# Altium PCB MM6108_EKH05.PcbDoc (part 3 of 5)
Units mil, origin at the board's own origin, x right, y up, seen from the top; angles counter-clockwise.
Board outline 6023.62 x 3425.2 mil, 4 copper layers (Top Layer, Ground Plane, Middle Layer, Bottom Layer), stack 76.15 mil thick; 212 components, 163 nets, 749 pads, 1477 vias.
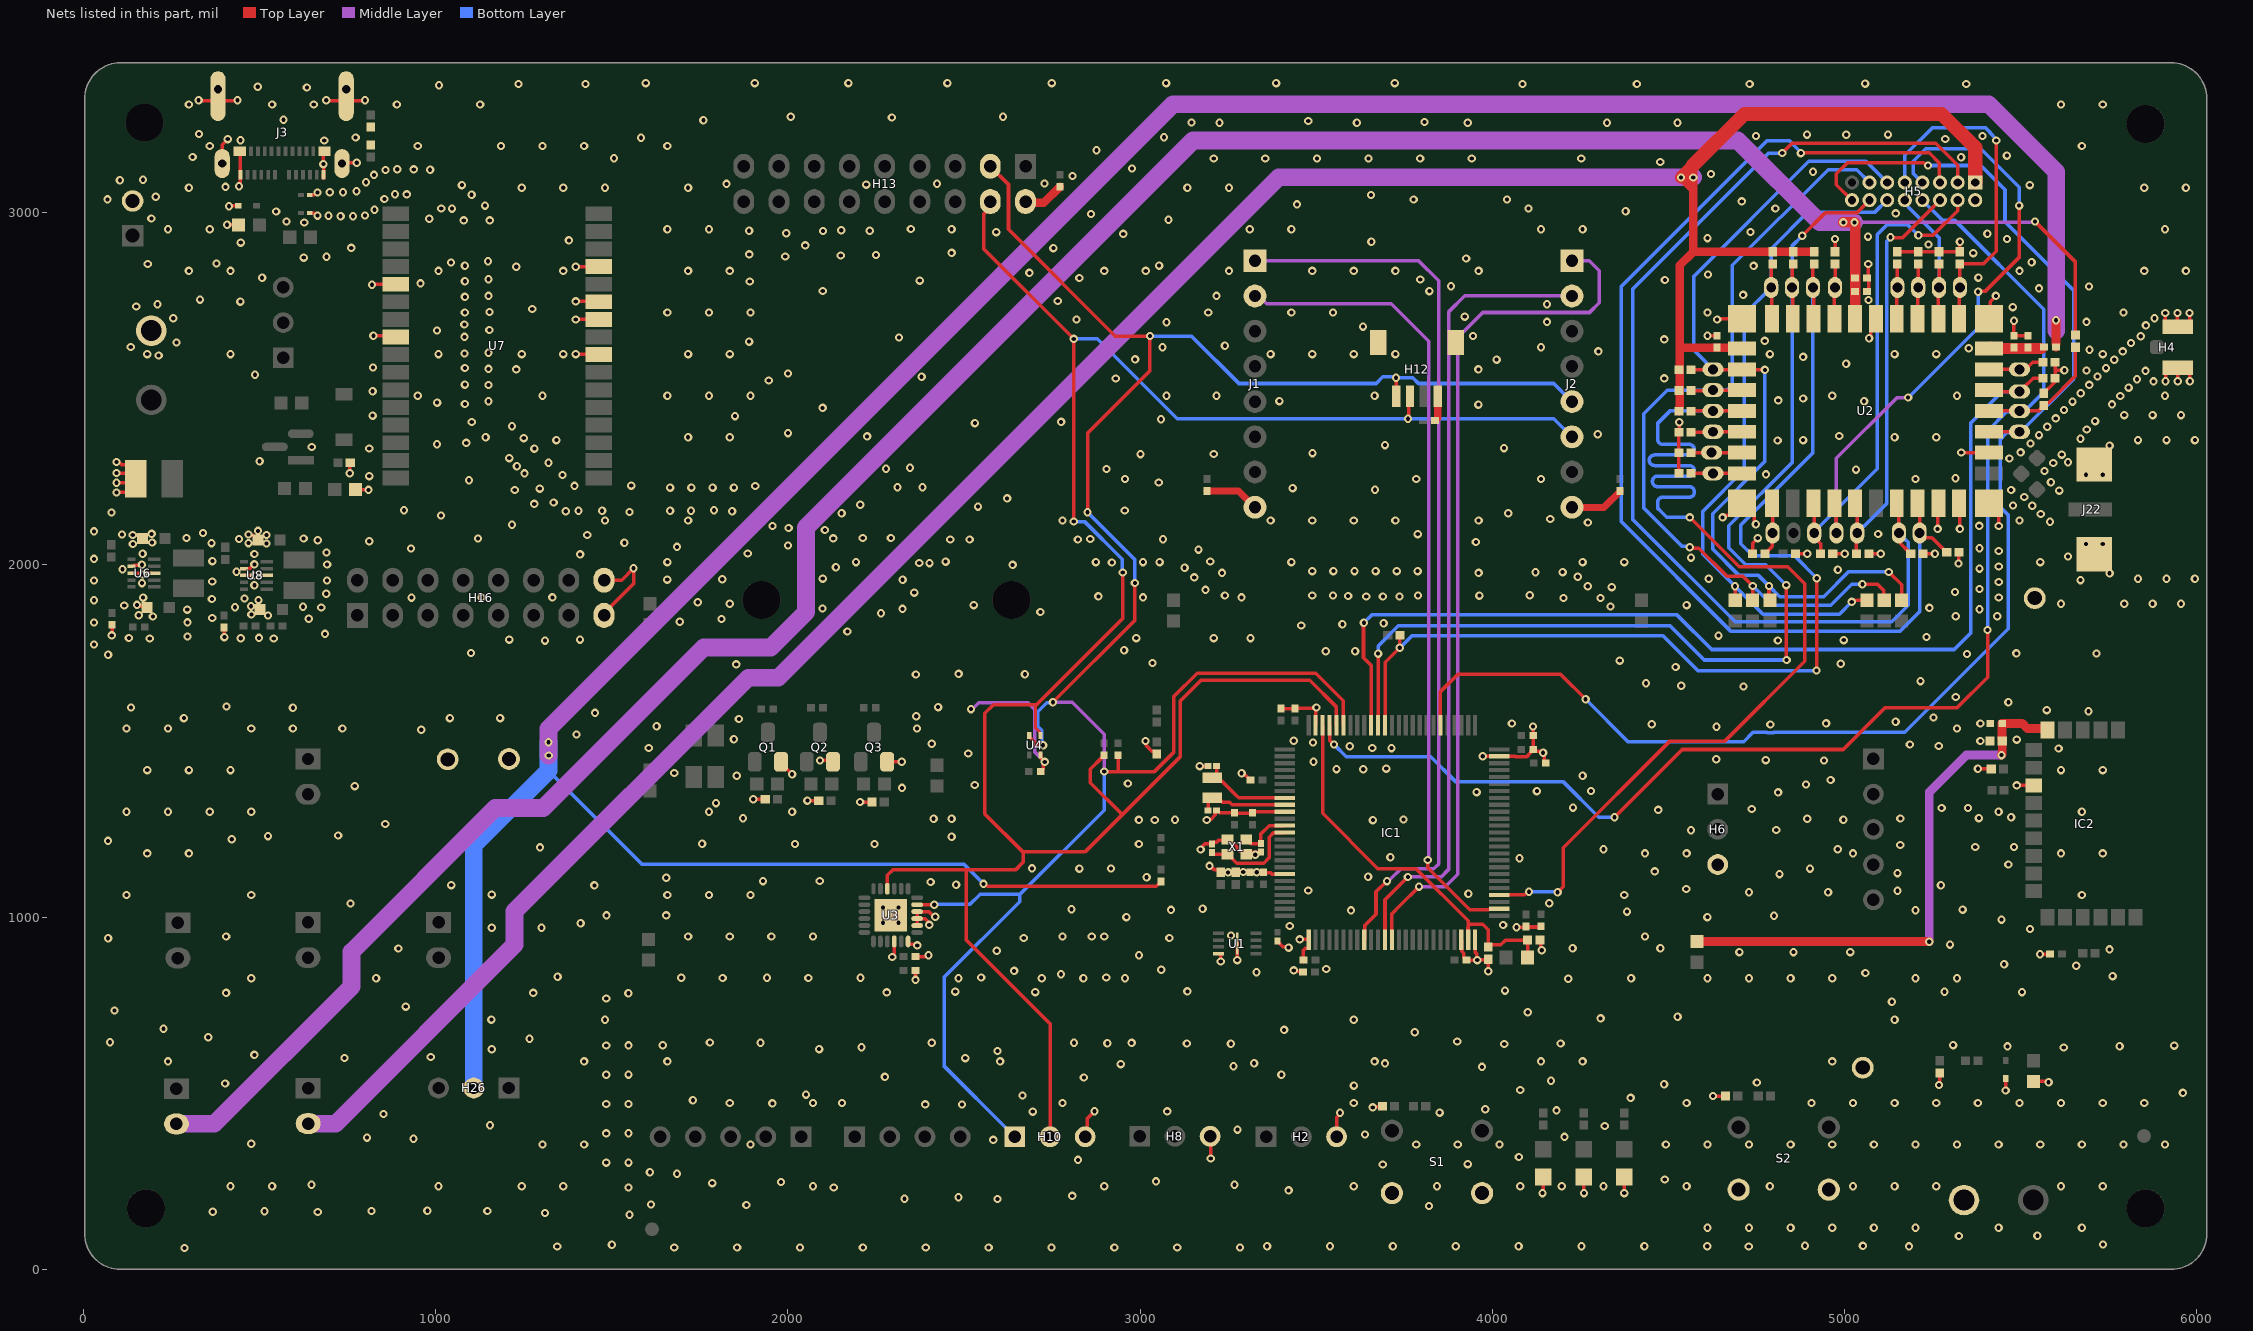
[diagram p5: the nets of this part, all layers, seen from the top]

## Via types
v1: diameter 23.62, hole 11.81, Top Layer to Bottom Layer, tented both sides, 1477 vias

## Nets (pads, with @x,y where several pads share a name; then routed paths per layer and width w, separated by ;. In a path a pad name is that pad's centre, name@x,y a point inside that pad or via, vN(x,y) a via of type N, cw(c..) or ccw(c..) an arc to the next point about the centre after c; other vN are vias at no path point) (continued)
GND: C1.1 C2.1 C3.1 C4.1 C5.1 C6.1 C7.1 C8.1 C9.2 C10.1 C11.1 C12.2 C13.2 C14.1 C15.1 C16.1 C17.1 C18.1 C19.2 C20.2 C21.1 C22.2 C23.2 C24.1 C25.1 C26.1 C27.2 C28.2 C29.2 C30.2 C31.2 C32.2 C33.2 C34.1 C35.1 C36.2 C37.1 C38.1 C39.1 C40.2 C41.1 C42.1 C43.1 C44.1 C45.1 C46.1 C47.1 C48.1 C49.2 D1.K D2.K D3.K D4.A D11.A D12.A H2.3 H4.2 H4.3 H5.2 H6.3 H8.3 H10.3 H11.1 H12.4 H12.5 H12.6 H13.2 H14.2 H15.1 H16.15 H16.16 IC1.10 IC1.19 IC1.26 IC1.48 IC1.50 IC1.74 IC1.99 IC2.8 J1.8 J2.8 J3.A1 J3.A12 J3.B1 J3.B12 J3.SH1 J3.SH2 J3.SH3 J3.SH4 J22.2 Q1.S Q2.S Q3.S R8.2 R11.1 R12.2 R14.1 R15.1 R16.1 R17.1 R18.1 R19.1 R20.1 R27.1 R28.1 R29.1 R30.1 R34.2 R37.2 R39.2 R40.2 R49.2 R52.2 R65.1 R66.1 R67.1 R69.2 R70.2 R72.2 R75.2 R77.2 S1.3 S1.4 S2.3 S2.4 TP1.1 TP2.1 TP3.1 TP4.1 U1.4 U1.9 U2.1 U2.2 U2.3 U2.12 U2.20 U2.26 U2.31 U2.37 U3.4 U3.6 U3.8 U3.9 U3.10 U3.25 U4.4 U6.2 U6.3 U6.8 U7.5 U7.8 U7.24 U7.26 U7.27 U7.29 U8.2 U8.3 U8.8 VS1.A X1.2 X1.4 | length 7882.7
  Top Layer w10: v1@81.26,1799.53 R72.2@81.26,1829.77 ; v1(93.7,2205.63) 122.32,2205.63 C49.2@147.83,2231.14 ; v1(93.7,2233.19) 136.02,2233.19 C49.2@147.83,2245 132.09,2260.75 v1(93.7,2260.75) ; v1(93.7,2292.24) 96.31,2289.64 103.2,2289.64 108.18,2284.65 122.32,2284.65 148.82,2258.16 C49.2@148.82,2231.14 ; U6.3@136.38,1976.69 160.25,1976.69 164.19,1972.76 v1(167.87,1972.76) ; U6.2@136.38,1996.38 142.91,1996.38 146.1,1999.57 165.06,1999.57 v1(165.81,2000.31) ; v1(139.61,2084.71) 158.28,2084.71 C42.1@167.87,2075.12 ; v1(151.75,1886.59) 155.39,1882.95 176.25,1882.95 C41.1@180.47,1878.74 ; v1@167.87,1970.71 v1(167.87,1972.76) ; U6.8@193.46,1976.69 193.39,1976.61 172.91,1976.61 169.06,1972.76 v1(167.87,1972.76) ; v1(326.77,3318.9) 327.36,3318.31 436.42,3318.31 v1(437.01,3318.9) ; J3.SH2@393.7,3139.37 393.7,3192.91 v1(409.45,3208.66) ; R77.2@399.49,1821.14 399.74,1820.88 399.74,1795.26 v1(400,1795) ; v1(407.75,2965.55) 439.93,2965.55 C40.2@440.47,2965 ; v1(412.84,3018) 413.83,3018.99 438.37,3018.99 VS1.A@439.36,3019.98 ; v1(441.44,3074.8) 441.44,3078.49 445.16,3082.21 445.16,3106.97 J3.A12@445.67,3107.48 ; J3.A12@445.67,3112.21 J3.B1@445.67,3181.31 ; U8.3@455.47,1970 v1(485,1970) v1@485,1967.96 ; U8.2@455.47,1989.69 472.33,1989.69 484.14,2001.5 v1(485,2001.5) ; v1(468.35,2086.26) 470.96,2083.65 481.51,2083.65 C44.1@494.84,2070.32 ; v1(496.76,1900.1) 496.76,1882.99 C43.1@506.28,1873.47 ; D12.A@640,3050 D12.A@640.91,3049.09 ; D11.A@642.2,2999.22 643.11,2998.32 656.48,2998.32 662.68,2992.11 v1@666.37,2992.11 ; D12.A@642.2,3050 643.11,3050.91 654.62,3050.91 660.79,3057.07 v1(664.47,3057.07) ; J3.A1@681.1,3098.43 681.38,3098.7 681.38,3106.97 J3.A1@681.89,3107.48 681.41,3107.96 681.41,3137.49 v1(681.1,3137.8) 681.1,3171.65 J3.B12@683.86,3174.41 ; v1(688.98,3318.9) 689.57,3318.31 798.62,3318.31 v1(799.21,3318.9) ; J3.SH1@733.07,3107.28 733.07,3130.71 744.09,3141.73 v1(775.59,3141.73) ; v1(755.76,2260.06) 756.54,2260.85 756.54,2289.22 R75.2@757.32,2290 ; R12.2@772.53,2214 773.53,2213 v1(809,2213) ; R70.2@814.21,3243.46 R70.2@815,3242.68 ; R69.2@815,3192.32 R69.2@820.27,3197.59 ; v1(818.9,2795.28) 820.47,2796.85 U7.5@886.38,2796.85 ; v1(822.83,2650.68) 882.54,2650.68 U7.8@886.38,2646.85 ; v1(1397.64,2598.43) 1461.18,2598.43 U7.24@1462.76,2596.85 ; v1(1397.64,2696.85) U7.26@1462.76,2696.85 ; v1(1397.64,2748.03) 1461.58,2748.03 U7.27@1462.76,2746.85 ; v1(1397.64,2846.46) 1462.36,2846.46 U7.29@1462.76,2846.85 ; H16.15@1477.76,1856.69 1477.76,1862.6 1561.57,1946.42 v1(1561.57,1990.43) 1527.84,1956.69 H16.16@1477.76,1956.69 ; H16.15@1497.1,1849.61 H16.15@1500.25,1846.46 ; v1(1901.57,1334.65) R65.1@1935.43,1334.65 ; Q1.S@1980.33,1440.94 1980.33,1435.69 1997.64,1418.39 1999.14,1418.39 2011.81,1405.72 v1(2011.81,1405.51) ; v1(2055.12,1330.71) R66.1@2087.4,1330.71 ; v1(2090.65,1444.88) 2124.02,1444.88 Q2.S@2127.95,1440.94 ; v1(2204.72,1326.77) R67.1@2238.58,1326.77 ; Q3.S@2281.51,1440.94 v1(2322.83,1440.94) ; v1(2296.16,887) 2296.16,890.69 2301.65,896.18 U3.4@2301.65,930.98 ; U3.6@2341.02,930.98 2341.02,925.25 2342.76,923.5 2359.81,923.5 2363.31,920 v1(2367,920) ; v1(2362,822) C38.1@2362,849 ; C37.1@2362,888 2391.31,888 2395.31,892 v1(2399,892) ; U3.8@2366.61,976.26 U3.9@2366.61,995.94 ; v1(2401,978) 2398.39,980.61 2398.39,986.86 2389.31,995.94 U3.9@2366.61,995.94 ; v1(2418,1001) 2414.31,1001 2400.41,1014.91 2367.33,1014.91 U3.10@2366.61,1015.63 U3.9@2366.61,995.94 ; U4.4@2716.54,1464.57 2717.44,1463.66 2717.44,1451.85 v1@2728.37,1440.92 ; C39.1@2718.11,1413.39 2724.93,1420.2 2724.93,1433.01 2727.7,1435.79 2727.7,1440.25 v1@2728.37,1440.92 ; v1(2728.8,1440.92) v1@2728.37,1440.92 ; H10.3@2848.9,371.72 2848.9,427.64 v1(2870.08,448.82) ; v1(3015.19,1500.19) 3017.61,1497.78 3017.61,1486.52 3033.14,1470.98 3040.04,1470.98 3047.24,1463.78 R8.2@3047.24,1462.99 ; v1(3169.17,1428.67) 3169.4,1428.9 3192.29,1428.9 C25.1@3192.52,1429.13 ; v1(3171.52,1192.19) 3171.52,1195.88 3180.47,1204.83 ; 3180.47,1204.87 3183.67,1208.07 C23.2@3203.74,1208.07 3203.74,1209.65 3207.01,1212.91 3216.85,1212.91 3222.16,1218.22 3245.78,1218.22 X1.4@3248.03,1220.47 3257.8,1210.71 3261.73,1210.71 3267.54,1204.9 3269.32,1204.9 3275.76,1198.45 3275.76,1194.9 3281.77,1188.9 3291.42,1188.9 X1.2@3301.18,1179.13 3306.69,1184.65 C22.2@3342.52,1184.65 ; v1(3188.98,1275.59) 3191.58,1278.2 3201.23,1278.2 3213.36,1290.33 3213.36,1299.88 C26.1@3216.63,1303.15 ; v1(3196.85,1145.67) 3198.99,1145.67 3209.52,1135.14 3221.14,1135.14 3228.35,1127.94 C17.1@3228.35,1127.56 ; v1(3200,315) 3200,363.78 H8.3@3214.17,377.95 ; C26.1@3216.93,1303.15 3218.5,1303.15 3225.13,1296.53 C3.1@3267.72,1296.53 ; U1.4@3222.64,895.67 3228.46,895.67 3228.54,895.59 v1(3228.54,874.21) ; C17.1@3232.28,1127.56 C21.1@3271.65,1127.56 3350.39,1127.56 3351.97,1125.98 3370.08,1125.98 3373.89,1122.17 3409.8,1122.17 IC1.19@3409.92,1122.05 ; C3.1@3267.72,1296.85 3270.08,1294.49 3316.54,1294.49 C2.1@3318.9,1296.85 ; v1(3275.59,877.95) U1.9@3275.59,925.2 ; v1(3287.84,1408.64) 3291.53,1408.64 3299.02,1401.14 3300.86,1401.14 3312,1390 C1.1@3313,1390 ; C2.1@3318.9,1296.53 3321.58,1299.21 IC1.10@3409.92,1299.21 ; C24.1@3389.76,932.68 3389.76,931.1 3404.87,915.99 3418.65,915.99 v1(3421.26,913.39) ; C14.1@3400,1592 C11.1@3440,1592 3441.5,1593.5 3498.5,1593.5 v1(3500,1595) 3498.94,1593.94 3498.94,1545.71 IC1.99@3498.03,1544.8 ; v1(3435.72,848.85) 3438.09,846.48 C5.1@3461.22,846.48 ; v1(3452.76,937.01) 3453.67,937.92 3477.44,937.92 3478.35,937.01 IC1.26@3478.35,935.51 3478.35,912.38 3477.44,911.48 3469.17,911.48 3463.31,905.62 C4.1@3463.31,874.02 ; H2.3@3557.38,376.69 3557.38,432.21 3566.93,441.76 v1(3566.93,444.88) ; v1(3660,460) 3661.3,461.3 3686.1,461.3 C19.2@3687.4,462.6 ; IC1.48@3911.42,935.51 3912.32,934.61 3912.32,903.79 3918.78,897.34 3918.78,885.16 3925.98,877.95 v1(3956.69,877.95) ; IC1.50@3950.79,935.51 3951.69,934.61 3951.69,899.44 3954.76,896.37 3954.76,879.88 v1(3956.69,877.95) ; v1(3972.44,1456.69) IC1.74@4019.21,1456.69 4064.55,1456.69 4066.43,1454.82 4096.42,1454.82 4109.43,1467.82 4109.43,1471.38 4114.43,1476.38 C8.1@4115.43,1476.38 ; v1(3988.19,846.46) C13.2@3988.19,880.31 3987.01,879.13 3957.87,879.13 v1(3956.69,877.95) ; v1(4068.34,971.2) 4068.74,971.59 C7.1@4134.97,971.59 ; C6.1@4100,972.61 4139.61,972.61 C7.1@4140,973 ; v1(4115.09,1541.3) 4115.26,1541.13 4115.26,1515.92 C10.1@4115.43,1515.75 ; C10.1@4115.75,1515.75 4115.75,1476.38 4120.75,1471.38 4135.59,1471.38 4140.05,1466.91 v1(4143.74,1466.91) 4146.35,1464.31 4146.35,1441.84 C15.1@4151.18,1437.01 ; C12.2@4134.45,935.04 4137.45,932.04 4137.45,908.64 v1(4140.05,906.03) ; v1(4141.73,216.54) 4143.7,218.5 D3.K@4143.7,262.2 ; D2.K@4258.86,262.2 4258.86,217.52 v1(4259.84,216.54) ; v1(4374.02,216.54) D1.K@4374.02,262.2 ; R28.1@4529.28,2259.84 R27.1@4529.28,2317.91 R20.1@4529.28,2376.97 4529.64,2377.33 4529.64,2404.64 v1(4530,2405) ; v1(4610.15,2650.71) 4610.22,2650.79 4637.4,2650.79 C31.2@4637.8,2651.18 ; v1(4625.98,492.13) C20.2@4661.81,492.13 ; v1(4637.8,2696.85) 4639.76,2698.82 U2.20@4708.66,2698.82 ; v1(4653.28,2135.04) 4656.96,2135.04 4662.75,2140.83 4674.29,2140.83 U2.12@4708.66,2175.2 4743.03,2140.83 4743.03,2123.7 4747.68,2119.05 v1(4747.68,2115.36) ; R29.1@4738.58,2031.5 4738.58,2061.42 v1(4753.13,2075.97) ; R30.1@4859.84,2031.5 v1(4893.7,2031.5) ; R40.2@4966.14,2031.5 v1(5000,2031.5) ; R19.1@4972.44,2888.98 v1(4972.44,2925.2) ; v1(5066.93,2854.33) 5066.93,2816.21 5068.18,2814.96 C29.2@5068.18,2775.59 ; R39.2@5068.5,2031.5 v1(5102.36,2031.5) ; v1(5069.35,2643.33) 5069.35,2647.02 5073.9,2651.56 5073.9,2684.13 U2.26@5088.58,2698.82 ; R18.1@5149.61,2889.13 R15.1@5326.77,2889.13 ; R37.2@5222.05,2031.5 v1(5255.91,2031.5) ; v1(5263.78,2102.36) 5263.78,2161.42 5271.65,2169.29 U2.3@5265.75,2175.2 ; v1(5267.72,523.62) 5269.69,525.59 C36.2@5269.69,557.87 ; U2.2@5310.12,2140.83 U2.2@5324.8,2155.51 ; v1(5322.83,2003.94) 5323.62,2004.72 5323.62,2034.65 R34.2@5324.41,2035.43 ; U2.2@5324.8,2175.2 5326.77,2173.23 v1(5326.77,2102.36) v1@5327.86,2103.45 ; R15.1@5326.77,2888.98 R15.1@5326.77,2889.13 ; v1(5326.77,2917.32) R15.1@5326.77,2889.13 ; v1(5330.71,2318.9) U2.37@5409.45,2318.9 ; v1(5377.95,1421.26) R49.2@5415.75,1421.26 ; U2.1@5409.45,2175.2 5437.01,2147.64 v1(5437.01,2110.24) ; U2.31@5409.45,2698.82 5412.69,2702.06 5412.69,2747.33 v1(5429.13,2763.78) ; v1(5456.69,507.87) D4.A@5456.69,541.34 ; v1(5480.31,2692.91) C28.2@5480.31,2650.86 C27.2@5519.69,2650.86 ; v1(5488.19,1374.02) IC2.8@5536.22,1374.02 ; R52.2@5535.43,533.46 5576.77,533.46 v1(5578.74,531.5) ; v1(5554.29,894.54) 5554.52,894.77 5582.45,894.77 C35.1@5582.68,895 ; C32.2@5565,2487.32 5565,2488.11 5597.32,2520.43 R11.1@5597.32,2530 5597.32,2552.5 ; R14.1@5597.32,2575 5597.32,2552.5 ; v1(5623.51,2552.74) 5623.27,2552.5 5597.32,2552.5 ; v1(5910,2715) 5910,2691.85 5925.67,2676.18 H4.2@5944.88,2676.18 ; v1(5910.76,2521.22) 5910.76,2544.37 5926.43,2560.04 H4.3@5944.88,2560.04 ; v1(5944.5,2715) 5944.5,2676.56 H4.2@5944.88,2676.18 ; v1(5945.26,2521.22) 5945.26,2559.66 H4.3@5944.88,2560.04 ; v1(5979,2715) 5979,2691.85 5963.33,2676.18 H4.2@5944.88,2676.18 ; v1(5979.76,2521.22) 5979.76,2544.37 5964.09,2560.04 H4.3@5944.88,2560.04
  Top Layer w20: C46.1@3188.98,2209.77 3279.4,2209.77 J1.8@3325.59,2163.58 ; C48.1@3837,2410 3838,2410 3844.65,2416.65 H12.4@3844.65,2479 ; J2.8@4225.59,2163.58 4317.02,2163.58 4362.2,2208.77 C47.1@4362.2,2209.77
  Top Layer w23.62: H13.2@2674.41,3031.5 2677.48,3028.43 2726.53,3028.43 C45.1@2771.65,3073.55
  Middle Layer w10: v1(2519.68,1590.55) 2523.37,1590.55 2541.08,1608.26 2681.74,1608.26 2700,1590 2700,1469.72 v1(2728.8,1440.92)
  other v1: 286.55,60.7 1677.17,62.24 1855.64,62.24 2034.12,62.24 2212.6,62.24 2391.08,62.24 2569.55,62.24 2748.03,62.24 2926.51,62.24 3104.99,62.24 3283.46,62.24 1345,65 4727.36,65.11 3360.3,65.54 3538.78,65.54 3717.26,65.54 3895.73,65.54 4074.21,65.54 4252.69,65.54 4431.17,65.54 4609.64,65.54 5182.36,65.4 5051.47,66.91 4887.17,67.35 1500,70 5733.15,70.84 5324.1,94.78 5546.93,95.48 4610.23,118.11 4728.34,118.11 4846.45,118.11 4964.56,118.11 5082.67,118.11 5200.78,118.11 5437,118.11 5673.22,118.11 1550,155 1310.31,159.96 665.17,163.15 366.82,163.79 514.08,165.06 817.53,165.7 1146.47,165.7 976.26,166.34 3820,180 1881.89,182.81 1611,184 2595,200 2330.71,200.79 2484.25,204.72 2807.09,208.66 3421.26,224.41 1547.24,232.28 2129.92,232.28 417.32,236.22 535.43,236.22 1007.87,236.22 1244.09,236.22 1362.2,236.22 2070.86,236.22 2897.64,236.22 3606.3,236.22 3842.52,236.22 4078.74,236.22 4196.85,236.22 4314.96,236.22 4551.18,236.22 4787.4,236.22 5023.62,236.22 5141.73,236.22 5259.84,236.22 5614.17,236.22 5732.28,236.22 647.23,240.26 3267.72,240.16 1785,245 1980.31,248.03 3045,250 4489.15,255.03 1685.04,271.65 1607.81,275.59 3688.62,297.74 3929.66,298.89 1484.25,303.15 1547.24,303.15 2823.37,311.05 4075.01,319.11 1303.15,354.33 1421.26,354.33 1893.7,354.33 3783.46,354.33 3901.57,354.33 4019.68,354.33 4492.12,354.33 4610.23,354.33 4728.34,354.33 4846.45,354.33 4964.56,354.33 5082.67,354.33 5200.78,354.33 5318.89,354.33 5437,354.33 5555.11,354.33 5673.22,354.33 5791.34,354.33 5909.45,354.33 476.38,356.81 2582.9,367.67 937,371 805,374 4204.4,376.3 3637.87,383.09 1484.25,386.28 1547.24,386.39 3276.28,396.88 4318.48,407 1154,409 851.69,441.07 3850,445 2695.03,447.83 3076.74,448.71 4181.52,451.55 3979.26,454.59 2493.96,467.92 2389.76,468.5 1484.25,469.42 1547.24,469.63 1955.74,471.26 1834.64,472.44 2070.86,472.44 2153.54,472.44 2779.53,472.44 3606.3,472.44 4551.18,472.44 4905.51,472.44 5023.62,472.44 5141.73,472.44 5259.84,472.44 5377.95,472.44 5496.06,472.44 5614.17,472.44 5732.28,472.44 5850.39,472.44 1730.03,480.42 4392.17,486.84 2665.91,493.86 2051.18,496.06 5959.94,501.23 4079.01,509.38 3606.53,521.79 4487.35,525.66 402,528 4750.61,530.59 4165.86,535.74 2840,545 2275.08,546.52 1484.25,552.55 1547.24,552.87 3400.65,552.8 3970,575 3264.75,576.68 2944.88,582.68 3695,585 3323.42,585.44 240.16,590.55 1421.26,590.55 1657.48,590.55 2602.36,590.55 3665.35,590.55 4137.79,590.55 4255.9,590.55 4964.56,590.55 741,600 2503.03,599.84 986,603 485,609 2595,620 1159,625 2088.47,625.21 5621.73,629.82 2208.76,630.63 5462.09,633.21 5780.4,633.7 5935.68,635.15 1484.25,635.68 1547.24,636.11 1644.45,636.53 5307.78,636.61 4033.34,639.87 3257.32,640.49 2906.64,641.86 3132.4,641.36 4193.5,641.38 1921.77,643.22 2407.97,643.29 2975.47,643.19 1778.22,644.25 2811.93,643.46 75,645 3900.07,647.06 1266,655 354,659 3779.53,673.23 3408.42,680 227,683 1158,709 1480.31,708.66 3606.3,708.66 5141.73,708.66 4307.09,712.6 4525.52,717.18 4100,730 88,735 915,746 5133.86,759.84 1484.25,769.1 1546.8,784.08 405,785 1277,785 2280.33,786.57 2701.84,787.21 5503.33,787.03 5283.03,788 2474.76,788.59 3133.86,789.21 4035.43,791.34 4215,825 476.38,826.77 830.71,826.77 2484.25,826.77 2720.47,826.77 2838.58,826.77 2956.69,826.77 4393.7,826.77 4610.23,826.77 4728.34,826.77 4846.45,826.77 4964.56,826.77 5200.78,826.77 5318.89,826.77 1696.79,827.77 1814.53,827.35 1940.22,828.18 2057.96,827.35 2205.95,828.13 2548.29,828.72 2903.31,828.83 1346,831 5760.51,832.64 2775.14,838.04 5058.61,841.26 3330.21,843.77 2641.89,847.38 3059.47,850.56 3527.92,852.84 5657.13,861.91 5452.39,866.37 2996.35,891.79 4700.79,900.79 4854.33,900.79 5015.75,900.79 2592.5,904.65 5751.52,908.56 894,911 4227.62,911.67 4476.58,911.87 5299.07,921.94 70,940 2669.29,940.94 3082.68,940.94 405,944.88 1716.53,944.88 1834.64,944.88 1952.75,944.88 2070.86,944.88 2779.53,944.88 2862.2,944.88 2897.64,944.88 4433.07,944.88 3257.83,947.83 5525.89,966.35 1159,970 1300,970 3424.4,974.65 4030.12,977.83 1411.26,982.46 2270.15,984.13 2313.46,984.13 5444.8,992.94 2960.63,1000 4610,1000 4799.21,1003.94 1485,1005 1654.6,1005 4381.89,1015.75 3598.41,1019.19 5200.79,1019.68 3087.21,1020.74 5334.75,1021.35 2804.8,1022.54 3177.17,1023.62 2270.15,1027.44 2313.46,1027.44 758,1039 4161.21,1039.41 122.05,1062.99 476.38,1062.99 1657.48,1062.99 1775.59,1062.99 1893.7,1062.99 4374.01,1062.99 5673.22,1062.99 1159,1064 3931.5,1066.57 4728.35,1070.87 4952.76,1070.87 5150,1075 3477.1,1075.45 4550,1080 1450.35,1090.17 1044,1091 5272.81,1090.55 2477.32,1092.1 2405,1100 1929.13,1102.36 2090.23,1102.39 1654.6,1111.72 3018.06,1113.34 3646.93,1114.48 4814.96,1122.05 5150,1125 3249.49,1127.22 3292.43,1128.04 3330.56,1127.49 4460.63,1129.92 2827.19,1137.8 2917.24,1137.94 4901.57,1137.8 2692.64,1138.38 5464.57,1149.61 4076.84,1167.07 3710,1170 3326.69,1177.16 181.1,1181.1 299.21,1181.1 4433.07,1181.1 4551.18,1181.1 5023.62,1181.1 5614.17,1181.1 5732.28,1181.1 4314.96,1192.91 4980.31,1192.91 1296,1198 5370.63,1199.21 5480.52,1198.96 5157.48,1204.72 2019.68,1207.81 2245.64,1207.81 2996.06,1207.81 1756.24,1208.35 69.61,1216.53 421,1221 2464.57,1228.35 524,1230 723,1232 4563.62,1246.49 4805.55,1247.38 856.69,1264.2 2996.14,1276.16 3041.24,1275.59 3660.42,1275.44 3098.68,1276.47 4996.06,1276.4 3747.25,1277.35 2413.39,1279.53 2464.57,1279.53 4893.7,1279.53 5157.88,1279.86 1872.1,1280.56 5380.76,1281.07 5472.44,1283.46 122.05,1299.21 240.16,1299.21 358.27,1299.21 476.38,1299.21 1775.59,1299.21 2011.81,1299.21 5437,1299.21 5673.22,1299.21 4470.38,1304.55 4736.22,1307.09 5275,1310 5350,1310 4228.35,1311.02 1795.61,1323.7 3955,1355 4811.02,1354.33 4125.98,1357.68 4279.53,1358.27 2323.66,1367.09 770,1372 2530.11,1375.18 4890.2,1376.47 2964.78,1379.43 4959.95,1389.39 1854.33,1401.57 4255.91,1401.57 1677.17,1409.45 181.1,1417.32 299.21,1417.32 417.32,1417.32 5614.17,1417.32 5732.28,1417.32 3557.16,1420.14 3633.03,1419.85 3698.27,1421.62 3491.76,1441.06 4940.94,1444.88 4775.76,1445.84 4635.3,1448.25 2511.81,1464.57 5607.16,1478.66 1604.87,1480.16 3658.51,1480.06 3713.12,1479.77 3595,1485 5266.89,1485.93 5185,1490 2408.31,1492.14 3490.33,1495.59 5385,1500 3435.72,1500.72 5488.19,1503.94 1846.44,1505.25 1399.43,1518.36 959,1532 122.05,1535.43 240.16,1535.43 476.38,1535.43 594.49,1535.43 734.94,1535.43 2366.14,1535.43 5318.89,1535.43 4635.8,1540.63 1627,1542 4788.98,1546.72 4452.06,1547.81 4055,1549.92 4947.26,1550.15 5385,1550 5144.57,1554.79 1860.53,1562.5 285,1565 1040,1565 1182.88,1565 5251.97,1566.93 2364.25,1570.25 1452,1580 5692.17,1584.73 5573.65,1587.77 135,1595 594.49,1594.49 2426.13,1596.24 405.99,1598.01 5464.57,1610.24 5315,1625 4712.8,1654.72 4536,1657 4435.77,1664.04 5215,1670 2363.15,1689.04 2672.51,1689.64 2484.37,1690.54 4520,1710 1853.22,1717.57 4988.71,1719.36 3034.85,1721.52 4361.1,1728.35 70,1745 5347.2,1747.27 5487.19,1748.78 5714.58,1748.54 1100,1750 3526.58,1754.69 3610,1755 2954.37,1757.89 30.01,1773.79 1310,1785 4810.21,1785.14 4997.16,1786.4 1208.66,1787.81 1409.45,1787.81 188.29,1791.1 540.33,1791.1 446.34,1791.95 2988.67,1792.15 3208.66,1792.15 3312.81,1792.15 128.9,1792.38 498.04,1792.81 5232.28,1795.28 295.1,1796.65 4641.73,1799.21 80,1800 685.44,1804.21 2168.52,1811.19 3457.12,1827.83 3573.84,1831.65 3690.99,1834.23 30.01,1836.43 295.1,1836.81 1692.91,1838.58 639.45,1847.17 1811.02,1846.46 365.4,1849.27 197.04,1853.55 5314.96,1854.33 5433.07,1854.33 156.89,1856.87 523.69,1856.53 476.57,1858.99 2264.16,1862.59 2716.54,1866.14 294.67,1873.13 5382.7,1874.02 2325.05,1875.27 2097.87,1876.18 5240.16,1877.95 675.13,1879.1 429.95,1879.99 623.2,1881.04 4335,1881.82 475.65,1882.69 115.79,1884.55 2527.56,1885.83 4551.18,1885.83 1834.64,1889.76 5614.17,1889.76 5793.31,1889.76 5874.02,1889.76 5954.72,1889.76 1743.94,1893.91 30.01,1899.73 364.44,1903.39 457.25,1904.66 4201.62,1906.05 4306.55,1906.08 169.23,1907.16 931.38,1906.98 5437.01,1907.26 1130.08,1907.46 1331.15,1907.93 3007.81,1907.81 3287.4,1907.92 2881.25,1910.61 3641.58,1910.48 3688.83,1910.48 3736.07,1910.48 3590.22,1911.67 3962.83,1912.7 3240.16,1913.39 3488.19,1913.39 3547.24,1913.39 3788.67,1913.39 4105.91,1913.96 689.18,1917.93 2358.27,1921.26 5313.02,1923.12 3185.04,1929.13 5382.7,1931.76 4338.58,1937.01 4270.3,1939.31 485,1942.44 166.21,1948.34 5437.01,1951.3 365.44,1952.76 30.01,1955.67 691.38,1955.93 5669.29,1956.69 1657.45,1958.27 2325.55,1957.92 1813.47,1959.13 2098.81,1961.01 4614.17,1960.63 5832.68,1960.63 5913.39,1960.63 5994.09,1960.63 3153.54,1964.57 4242.11,1966.5 5751.97,1976.38 3232.28,1977.42 3960.63,1977.42 4122.29,1979.25 4199.15,1979.59 434.54,1980.69 3488.19,1982.42 3548.23,1982.42 3608.27,1982.42 3668.31,1982.42 3728.35,1982.42 3787.4,1982.42 4980.56,1986.16 110.85,1987.75 5382.7,1989.5 3125.98,1992.13 2136.01,1993.54 5437.01,1995.33 2637.8,2000 691.66,2001.1 2372.79,2005.16 2401.61,2005.11 2919.56,2007.01 1657.48,2007.87 2192.91,2007.87 2874.02,2007.87 3007.81,2007.87 3055.12,2007.87 3429.13,2007.87 4255.91,2007.87 4374.01,2007.87 5555.11,2007.87 2447.44,2009.26 3198.67,2009.69 365.95,2010.72 30.01,2017.1 4563.34,2020.57 5633.86,2023.62 1410,2030 485.02,2030.89 167.87,2031.81 1885.98,2032.31 690,2035 5437.01,2039.37 3165.35,2043.31 929.96,2046.41 5382.7,2047.24 1685.04,2051.18 2000,2055.12 5685.04,2059.06 5732.28,2059.06 140.07,2059.43 519.69,2060.96 363.47,2061.91 468.46,2061.8 1535.43,2062.99 194.77,2063.8 3952.81,2065 811.02,2066.93 665,2070 2460.63,2072.05 2515.75,2072.05 2822.83,2072.05 3064.87,2072.62 441.29,2073.64 2858.22,2073.73 625,2075 1120,2075 2128.56,2075.37 2212.09,2076.21 2292.02,2076.2 292.45,2076.62 519.49,2085.01 1430,2085 109.27,2086.33 3788.02,2087.27 193.5,2088.15 5094.77,2087.71 339.02,2090.35 30.01,2095.23 495.25,2096.71 2104.75,2099.21 2001.86,2104.53 1956.24,2110.69 5381.92,2110.73 1216.54,2114.17 4270.69,2120.25 5582.51,2122.63 1480.31,2125.98 1716.53,2125.98 2779.53,2125.98 3370.08,2125.98 3488.19,2125.98 3606.3,2125.98 3724.41,2125.98 3960.63,2125.98 5496.06,2125.98 4164.17,2130.29 1015,2140 5556.48,2144.68 2152.38,2146.83 4044.68,2146.41 79.59,2148.66 1550,2150 1369.03,2152.45 1841.47,2152.32 1405.51,2153.54 1472.44,2153.54 1665.35,2153.54 1724.41,2153.54 2955.85,2154.27 910,2155 1790,2155 2539.37,2165.35 5532.14,2167.87 5477.84,2168.78 2205.22,2170.66 1279.53,2173.23 1334.65,2177.17 2622.05,2188.98 5509.59,2192.81 5608.87,2210.75 1224.41,2212.6 5472.44,2212.6 3666.68,2213.32 1295.28,2216.54 3432.69,2217.88 1665.35,2219.27 1725.72,2219.27 1786.09,2219.27 1846.46,2219.27 2311.02,2220.47 2381.89,2220.47 1907.05,2224.12 1393.7,2224.41 1555,2225 3052.6,2234.04 5585.12,2234.55 1094.49,2240.16 2956.69,2244.09 3783.46,2244.09 4137.79,2244.09 5200.78,2244.09 5314.42,2245.83 811.02,2251.97 1360,2255 5685.04,2255.91 5732.28,2255.91 4776.63,2256.93 1251.97,2259.84 5567.16,2266.82 5032.07,2270.54 2904,2272.2 2278.36,2272.82 2346.46,2275.59 1230.36,2280.12 1320,2290 5592.08,2289.39 5633.86,2291.34 500.13,2294.19 5467.47,2302.15 1208.66,2303.15 5615.86,2313.17 3000.55,2314.44 3208.66,2314.96 3488.82,2317.33 5499.35,2319.41 1280,2330 811.02,2330.71 4032.63,2331.59 648.05,2334.6 5751.97,2338.58 3695,2340 1003.55,2342.52 5527.59,2344.57 1086.61,2346.46 4809.41,2353.02 1342.52,2354.33 4881.89,2354.33 5832.68,2354.33 5913.39,2354.33 5994.09,2354.33 5669.29,2358.27 1250,2360 1141.73,2362.2 1716.53,2362.2 1834.64,2362.2 5141.73,2362.2 5259.84,2362.2 2224.63,2364.95 4984.25,2366.14 5551.37,2368.34 4298.9,2370.75 2000,2374.02 5687.18,2384.49 5575.14,2392.12 1216.54,2393.7 2530.53,2402.44 1102.36,2405.51 2775.43,2406.05 5710.96,2408.26 3059.06,2413.39 5598.92,2415.89 1849.46,2422.37 820.84,2423.86 5793.31,2425.2 5874.02,2425.2 5954.72,2425.2 5622.69,2439.67 2098.42,2445.78 3960,2455 5758.51,2455.81 1082.68,2456.69 1003.94,2460.63 5646.47,2463.44 1149.61,2464.57 3395,2465 5055.12,2464.57 4811.46,2467.06 4881.89,2472.44 5782.28,2479.59 948.82,2480.31 1303.15,2480.31 1657.48,2480.31 1775.59,2480.31 1893.7,2480.31 3074.8,2480.31 3216.54,2480.31 3665.35,2480.31 4964.56,2480.31 5318.89,2480.31 5909.45,2480.31 5670.24,2487.21 820.94,2492.97 5806.05,2503.36 1149.61,2510.5 5694.01,2510.99 1082.68,2511.81 5876.44,2521.06 1945.46,2523.51 5829.83,2527.13 2930.47,2529.27 4487.7,2529.55 2379.46,2533.92 5717.79,2534.76 487.05,2539.86 2000,2543.31 5853.6,2550.91 5686.19,2551.97 1228.35,2555.12 3960,2555 1149.61,2556.43 1082.68,2559.06 5741.56,2558.54 822.11,2560.57 5003.94,2570.87 4011.81,2582.68 5765.34,2582.31 2985.39,2583.51 4881.89,2590.55 213.28,2594.37 181.1,2598.42 417.32,2598.42 1007.87,2598.42 1244.09,2598.42 1362.2,2598.42 1716.53,2598.42 1834.64,2598.42 3370.08,2598.42 3488.19,2598.42 3606.3,2598.42 3724.41,2598.42 4787.4,2598.42 5141.73,2598.42 5259.84,2598.42 5732.28,2598.42 1081.46,2600.19 1149.61,2602.36 4300.52,2606.28 5789.11,2606.09 5694.91,2610.87 5352.27,2615.01 3062.99,2618.11 4137.8,2618.11 134.34,2618.72 3240.16,2622.05 5812.89,2629.86 264.19,2631.26 1889.76,2633.86 4772.83,2636.03 4487.77,2640.16 2314.96,2645.67 1081.46,2647.43 3944.88,2649.61 5840.29,2649.34 1003.55,2665.35 1152.35,2666.67 3632.19,2676.47 5855,2680 1081.22,2682.23 3074.8,2688.98 4155,2690 5686.19,2689.93 2818.9,2696.85 255,2700 5879.46,2700.01 3921.26,2704.72 1082.68,2716.54 1657.48,2716.53 1775.59,2716.53 1893.7,2716.53 3192.91,2716.53 3429.13,2716.53 3547.24,2716.53 4610.23,2716.53 5791.34,2716.53 1152.62,2718.11 1274.13,2726.51 5476.87,2731.87 149.84,2733.81 210,2740 4155,2740 445.41,2747.45 2765.9,2749.27 5067.4,2752.03 330.99,2753.01 1082.68,2760.83 1149.61,2763.78 3216.54,2763.78 4711.53,2766.53 2098.59,2777.79 3820.71,2777.29 5551.68,2785 3882.18,2791.25 5693.22,2790.42 956.69,2799.21 1082.68,2805.12 1891.62,2804.51 2374.02,2807.09 4489.3,2808.72 3795,2810 1149.61,2811.02 507.17,2815 2827.2,2814.44 5379.34,2815.43 4611.77,2824.31 2685.34,2828.95 299.21,2834.64 417.32,2834.64 1007.87,2834.64 1362.2,2834.64 1716.53,2834.64 1834.64,2834.64 2897.64,2834.64 3015.75,2834.64 3251.97,2834.64 3488.19,2834.64 3606.3,2834.64 3724.41,2834.64 3960.63,2834.64 5496.06,2834.64 5850.39,2834.64 5968.5,2834.64 1228.35,2846.46 4741.44,2848.97 1082.68,2849.41 3053.61,2849.67 182.26,2854.35 377.7,2855.65 1043.31,2858.27 5530.59,2859.32 1148.4,2862.2 3925.2,2870.08 625.31,2872.34 690,2875 1992.31,2875.63 2149.58,2878.51 2250,2880 1889.93,2881.6 5365,2885 2464.57,2885.83 760,2900 2753.39,2899.32 2048.86,2907.18 5237.63,2909.76 446.46,2914.99 3656.21,2917.5 1377.95,2921.26 5460.77,2925.17 4610.33,2927.71 5066.07,2931.93 2951.73,2939.75 5405,2940 1995.18,2941.35 2591.42,2944.67 4732.28,2944.88 2099.15,2947.87 1889.76,2948.82 2232.28,2948.82 2151.38,2949.96 240.16,2952.75 358.27,2952.75 1657.48,2952.75 1775.59,2952.75 2464.57,2952.76 3311.02,2952.75 3429.13,2952.75 4137.79,2952.75 4255.9,2952.75 5909.45,2952.75 2348.91,2953.52 626.85,2971.91 576.2,2975.01 1079.65,2978.1 1153.25,2978.18 3080,2980 192.59,2983.2 981.57,2982.55 730,2990 765,2990 664.53,2991.45 695.71,2991.36 799.05,2991.92 2860.26,2996 5144.83,2997.96 546.88,3003.31 4377.95,3003.94 826.14,3008.12 1015.7,3011.96 1046.24,3011.51 4102.36,3011.81 4803.15,3011.81 1140,3020 3444.88,3023.62 4707.72,3032.02 68.07,3037.82 3776.21,3037.5 4041.21,3037.5 854.07,3038.57 205,3045 3655,3050 1101.8,3050.62 884.51,3052.25 917.75,3051.97 699.19,3057.9 736.9,3057.9 775.16,3060.69 299.21,3070.86 1244.09,3070.86 1362.2,3070.86 1480.31,3070.86 1716.53,3070.86 3133.86,3070.86 3251.97,3070.86 5850.39,3070.86 5968.5,3070.86 403.05,3073.19 1074.24,3078.18 5525.33,3078.17 2222.34,3079.53 1825.67,3081.79 2423.25,3082.17 2728.35,3082.68 802.2,3086.38 103.31,3091.86 168.7,3093.54 2807.56,3104.18 824.75,3107.28 4620.58,3109.78 4909.89,3116.31 857.55,3121.3 984.08,3121.86 890.66,3123.2 937.71,3122.98 2976.8,3125.21 4476.38,3143.84 3208.66,3153.54 3355.12,3153.54 3501.57,3153.54 3648.03,3153.54 3794.49,3153.54 3940.94,3153.54 4251.97,3153.54 1506.09,3154.37 5330.37,3157.14 309.92,3157.83 5460.2,3161.8 2876,3177 358.27,3188.98 948.82,3188.98 1185.04,3188.98 1303.15,3188.98 1421.26,3188.98 1657.48,3188.98 5673.22,3188.98 683.37,3204.8 445.52,3205.44 5285.13,3209.14 1582.68,3212.6 772.48,3213.33 3067.35,3213.9 4748.12,3217.4 5390.85,3217.62 5004.3,3220.94 4892.91,3221.57 5122.78,3221.41 327.72,3223.12 3225,3255 3615,3255 3930,3255 4325,3255 4525,3255 3145.67,3255.91 3806.79,3257.51 3476.84,3259.98 1759.84,3262.22 567.92,3263.76 2295,3270 2007.87,3272.19 2610.24,3272.19 299.21,3307.09 535.43,3307.09 653.54,3307.09 889.76,3307.09 1125.98,3307.09 5614.17,3307.09 5732.28,3307.09 634.06,3355.07 494.65,3357.25 1009.36,3361.65 1235,3365 1425,3365 4085,3365 4410,3365 4730,3365 5345,3365 5057.82,3366.3 1596.28,3367.81 1905.48,3367.81 2171.32,3367.81 2452.46,3367.81 2748.91,3367.81 3073.4,3367.75 3385.83,3367.75 3722.39,3367.75
I2C_SCL: H10.1 H12.1 H13.3 IC1.95 J2.5 R82.2 U3.11 U4.2 | length 6513
  Top Layer w10: U3.11@2366.61,1035.31 2414.68,1035.31 v1(2415,1035) ; H13.3@2558.98,3146.92 H13.3@2574.41,3131.5 2625.98,3079.92 2625.98,2952.76 2929.13,2649.61 v1(3027.56,2649.61) 3027.56,2551.18 2850.39,2374.02 v1(2850.39,2149.61) ; U4.2@2685.04,1515.75 2685.94,1514.84 2685.94,1510.91 2707.42,1489.43 2723.03,1489.43 v1(2724.27,1488.19) ; v1(2751.97,1610.24) 2985,1843.27 2985,1948.67 v1(2984.84,1948.83) ; v1(2897.64,1413.39) 2937.01,1413.39 ; R82.2@2937.01,1459.38 2937.01,1413.39 ; IC1.95@3576.77,1544.8 3576.77,1614.17 3498.03,1692.91 3161.42,1692.91 3094.49,1625.98 3094.49,1467.51 3040.36,1413.39 2937.01,1413.39 ; v1(3725.85,2531.18) 3726.19,2530.84 3726.19,2479.34 H12.1@3726.54,2479
  Middle Layer w10: v1(2751.97,1610.24) 2807.09,1610.24 2897.64,1519.69 v1(2897.64,1413.39)
  Bottom Layer w10: v1(2415,1035) 2416,1036 2516,1036 2545.5,1065.5 2657.93,1065.5 2657.93,1043.93 2443,829 2443,577.39 2629.92,390.47 H10.1@2657.48,390.47 ; 2657.93,1064.27 2897.64,1303.98 v1(2897.64,1413.39) ; v1(2724.27,1488.19) 2721.67,1490.8 2721.67,1499.66 2720.47,1500.86 2720.47,1529.91 2708.79,1541.59 2708.79,1567.08 2708.79,1582.81 2734.38,1608.39 2750.13,1608.39 v1(2751.97,1610.24) ; v1(2850.39,2149.61) 2985,2015 2985,1948.98 v1(2984.84,1948.83) ; v1(3027.56,2649.61) 3145.67,2649.61 3280.28,2515 3670,2515 3688.78,2533.78 3723.24,2533.78 v1(3725.85,2531.18) 3726.35,2531.68 3773.32,2531.68 3790,2515 4174.17,2515 J2.5@4225.59,2463.58
I2C_SDA: H10.2 H12.2 H13.4 IC1.96 J2.6 R85.2 U3.16 U4.1 | length 6809.5
  Top Layer w8: 2702.56,1603.27 2702.56,1600.2 2702.56,1537.6 2714.63,1525.53 2714.63,1521.59 U4.1@2716.54,1519.68
  Top Layer w10: U3.16@2281.96,1080.59 2281.96,1118.96 2297,1134 2505.92,1134 ; H13.4@2574.41,3031.5 2574.41,3014.5 2555.12,2995.2 2555.12,2897.64 v1(2811.02,2641.73) v1(2811.02,2123.14) ; 2667.35,1185 2667.35,1155.59 2645.75,1134 2505.92,1134 ; 2702.56,1600.2 2950.18,1847.82 v1(2950.18,1978.48) ; 2702.56,1603.27 2583.58,1603.27 2559.06,1578.74 2559.06,1293.01 2667.06,1185 2843.02,1185 3114.17,1456.16 3114.17,1614.17 3172.42,1672.42 3481.12,1672.42 3557.09,1596.46 IC1.96@3557.09,1544.8 ; H10.2@2744.09,380.66 2744.09,696.85 2505.92,935.02 2505.92,1134 ; R85.2@2897.64,1459.38 2897.64,1458.38 2892.64,1453.38 2891.64,1453.38 2858.27,1420.01 2858.27,1381.89 2947.25,1292.91 ; v1(3760,2415) 3762.61,2417.61 3762.61,2475.7 H12.2@3765.91,2479
  Bottom Layer w10: v1(2811.02,2123.14) 2841.86,2123.14 2948.54,2016.46 2948.54,1980.11 v1(2950.18,1978.48) ; v1(2811.02,2641.73) 2878.27,2641.73 3105,2415 v1(3760,2415) 4174.17,2415 J2.6@4225.59,2363.58
MIKRO_AN: IC1.34 J1.1 | length 2561.3
  Top Layer w10: IC1.34@3635.83,935.51 3636.73,936.42 3636.73,975.9 3669.29,1008.46 3669.29,1071.93 3699.72,1102.36 v1(3700.79,1102.36)
  Middle Layer w10: J1.1@3325.59,2863.58 3789.96,2863.58 3847.03,2806.51 3847.03,1151.06 3833.76,1137.8 3740.16,1137.8 3711.54,1109.17 3711.28,1109.17 3704.47,1102.36 v1(3700.79,1102.36)
MIKRO_INT: IC1.37 J2.2 | length 2281.6
  Top Layer w10: IC1.37@3694.88,935.51 3694.88,1049.21 v1(3759.84,1114.17)
  Middle Layer w10: v1(3759.84,1114.17) 3854.33,1114.17 3875.31,1135.15 3875.31,2717.83 3921.06,2763.58 J2.2@4225.59,2763.58
MIKRO_PWM: IC1.38 J2.1 | length 2453.9
  Top Layer w10: IC1.38@3714.57,935.51 3714.57,1009.84 3736.89,1032.17 v1(3791.34,1086.61)
  Middle Layer w10: v1(3791.34,1086.61) 3866.14,1086.61 3901.59,1122.06 3901.59,2645.69 3972.44,2716.54 4275.59,2716.54 4303.15,2744.09 4303.15,2834.65 4274.21,2863.58 J2.1@4225.59,2863.58
MIKRO_RST: IC1.52 J1.2 | length 2296.6
  Top Layer w10: v1(3816.26,1162.1) 3816.26,1140.07 3935.49,1020.84 3989.32,1020.84 3991.19,1022.72 4018.31,1022.72 IC1.52@4019.21,1023.62
  Middle Layer w10: J1.2@3325.59,2763.58 3336.91,2763.58 3358.95,2741.55 3712.8,2741.55 3819.26,2635.08 3819.26,1174.73 3818.87,1174.34 3818.87,1164.71 v1(3816.26,1162.1)
MM_BUSY: IC1.91 pad.31@5496.06,2492.13 R11.2 U2.34 | length 3035.3
  Top Layer w10: v1(3634.87,1835.92) 3633.79,1834.85 3633.79,1736.29 3655.51,1714.57 IC1.91@3655.51,1544.8 ; U2.34@5409.45,2496.06 5413.39,2492.13 pad.31@5496.06,2492.13 5497.95,2492.13 5511.8,2505.98 5511.8,2507.12 5534.69,2530 R11.2@5562.68,2530
  Bottom Layer w10: v1(3634.87,1835.92) 3656.91,1857.96 4523.92,1857.96 4622.05,1759.84 5311.02,1759.84 5358.27,1807.09 5358.27,2403.27 5447.13,2492.13 pad.31@5496.06,2492.13
MM_GPIO_1: pad.31@5496.06,2555.12 R14.2 U2.33 | length 161.5
  Top Layer w10: U2.33@5409.45,2555.12 pad.31@5496.06,2555.12 5514.18,2555.12 5534.06,2575 R14.2@5562.68,2575
MM_GPIO_2: H5.9 pad.31@5326.77,2787.4 R15.2 U2.30 | length 975.9
  Top Layer w10: U2.30@5324.8,2698.82 5324.8,2785.43 pad.31@5326.77,2787.4 R15.2@5326.77,2854.33 5393.7,2854.33 5430,2890.63 v1(5430,3205)
  Bottom Layer w10: H5.9@5170.47,3085.43 5170.47,3162.6 5248.31,3240.43 5400.3,3240.43 5413.66,3227.07 5413.66,3225.02 5430,3208.69 v1(5430,3205)
MM_GPIO_3: H5.10 pad.31@5267.72,2787.4 R16.2 U2.29 | length 434.8
  Top Layer w10: U2.29@5265.75,2698.82 5265.75,2785.43 pad.31@5267.72,2787.4 R16.2@5267.72,2844.49
  Bottom Layer w10: H5.10@5170.47,3035.43 5170.47,3027.32 5180.69,3017.09 5180.69,3016.16 5267.72,2929.13 pad.31@5267.72,2787.4
MM_GPIO_4: pad.31@5208.66,2787.4 R17.2 U2.28 | length 152.8
  Top Layer w10: U2.28@5206.69,2698.82 5206.69,2785.43 pad.31@5208.66,2787.4 R17.2@5208.66,2850.79
MM_GPIO_5: pad.31@5149.61,2787.4 R18.2 U2.27 | length 152.8
  Top Layer w10: U2.27@5147.64,2698.82 5147.64,2785.43 pad.31@5149.61,2787.4 R18.2@5149.61,2850.79
MM_GPIO_6: pad.31@4972.44,2787.4 R19.2 U2.24 | length 156.3
  Top Layer w10: U2.24@4970.47,2698.82 4970.47,2785.43 pad.31@4972.44,2787.4 R19.2@4972.44,2854.33
MM_GPIO_7: pad.31@4625.98,2377.95 R20.2 U2.15 | length 145.1
  Top Layer w10: R20.2@4563.92,2376.97 4625,2376.97 pad.31@4625.98,2377.95 U2.15@4708.66,2377.95
MM_GPIO_8: pad.31@4622.05,2318.9 R27.2 U2.14 | length 145.1
  Top Layer w10: R27.2@4563.92,2317.91 4564.91,2318.9 pad.31@4622.05,2318.9 U2.14@4708.66,2318.9
MM_GPIO_9: pad.31@4625.98,2259.84 R28.2 U2.13 | length 144.7
  Top Layer w10: R28.2@4563.92,2259.84 pad.31@4625.98,2259.84 U2.13@4708.66,2259.84
MM_GPIO_10: pad.31@4795.28,2090.55 R29.2 U2.11 | length 154.1
  Top Layer w10: R29.2@4773.23,2031.5 4774.02,2031.5 4781.22,2038.7 4781.22,2039.49 4794.03,2052.3 4794.03,2089.31 pad.31@4795.28,2090.55 4795.28,2173.23 U2.11@4793.31,2175.2
MM_JTAG_TCK: H5.5 pad.31@5212.6,2090.55 R34.1 U2.4 | length 3236.5
  Top Layer w10: v1(4875.51,3168.97) 4876.28,3169.75 5239.7,3169.75 5267.72,3141.73 5267.72,3088.19 H5.5@5270.47,3085.43 ; U2.4@5206.69,2175.2 5212.6,2169.29 pad.31@5212.6,2090.55 5226.34,2076.81 5247.6,2076.81 5288.98,2035.43 R34.1@5289.76,2035.43
  Bottom Layer w10: v1(4875.51,3168.97) 4875.51,3171.74 4842.52,3204.72 4779.72,3204.72 4366.14,2791.14 4366.14,2122.05 4677.17,1811.02 5156.02,1811.02 5212.6,1867.6 pad.31@5212.6,2090.55
MM_JTAG_TDI: H5.3 pad.31@5153.54,2090.55 R37.1 U2.5 | length 3122.7
  Top Layer w10: v1(4822.83,3169.29) 4850.39,3196.85 5258.4,3196.85 5320.47,3134.77 H5.3@5320.47,3085.43 ; U2.5@5147.64,2175.2 5153.54,2169.29 pad.31@5153.54,2090.55 5159.28,2084.81 5159.28,2059.61 5179.41,2039.49 5179.41,2038.7 5186.61,2031.5 R37.1@5187.4,2031.5
  Bottom Layer w10: v1(4822.83,3169.29) 4784.29,3169.29 4397.64,2782.64 4397.64,2129.92 4688.98,1838.58 5133.58,1838.58 5180,1885 5180,2064.09 5173.29,2070.8 5171.41,2070.8 5153.54,2088.67 pad.31@5153.54,2090.55
MM_JTAG_TDO: H5.4 pad.31@4913.39,2090.55 R40.1 U2.9 | length 1384
  Top Layer w10: U2.9@4911.42,2175.2 4913.39,2173.23 pad.31@4913.39,2090.55 4913.39,2077.8 4931.5,2059.69 R40.1@4931.5,2031.5 ; v1(5209.06,2935.63) 5250.59,2935.63 5320.47,3005.51 H5.4@5320.47,3035.43
  Bottom Layer w10: pad.31@4913.39,2090.55 4913.39,2094.49 5092.16,2273.27 5092.16,2937.89 5119.27,2965 5179.69,2965 v1(5209.06,2935.63)
MM_JTAG_TMS: H5.6 pad.31@5035.43,2090.55 R39.1 U2.7 | length 1211.9
  Top Layer w10: U2.7@5029.53,2175.2 5035.43,2169.29 pad.31@5035.43,2090.55 5033.07,2088.19 R39.1@5033.07,2031.5 ; v1(5130,2930) 5131.04,2928.96 5164,2928.96 H5.6@5270.47,3035.43
  Bottom Layer w10: pad.31@5035.43,2090.55 5035.43,2092.43 5053.3,2110.3 5055.18,2110.3 5118.61,2173.72 5118.61,2917.33 5130,2928.72 v1(5130,2930)
MM_JTAG_TRST_N: H5.7 pad.31@4976.38,2090.55 U2.8 | length 1745.4
  Top Layer w10: U2.8@4970.47,2175.2 4976.38,2169.29 pad.31@4976.38,2090.55 ; v1(5378.76,2775.59) 5379.44,2776.27 5398.32,2776.27 5496.06,2874.02 5496.06,3018.94 v1(5495,3020)
  Middle Layer w10: pad.31@4976.38,2090.55 4976.38,2303.15 5148.23,2475 v1(5180,2475)
  Bottom Layer w10: v1(5180,2475) 5378.76,2673.76 v1(5378.76,2775.59) ; H5.7@5220.47,3085.43 5194.91,3110.99 5194.91,3146 5230.49,3181.57 5385.72,3181.57 5495,3072.29 v1(5495,3020)
MM_RESET_N: C32.1 H5.8 IC1.97 pad.31@5496.06,2437.01 R46.2 U2.35 | length 4146.8
  Top Layer w10: IC1.97@3537.4,1544.8 3537.4,1502.6 v1(3550,1490) ; v1(4346.46,1283.46) 4538.95,1475.96 4995.64,1475.96 5114.17,1594.49 5318.9,1594.49 5405.51,1681.1 v1(5405.51,1814.96) ; U2.35@5409.45,2437.01 pad.31@5496.06,2437.01 5550.12,2437.01 5565,2451.89 C32.1@5565,2452.68 5565,2453.46 5572.2,2460.67 5579.1,2460.67 5655,2536.57 R46.2@5655,2617.68
  Bottom Layer w10: v1(3550,1490) 3585,1455 3825,1455 3895,1385 4200,1385 4301.54,1283.46 v1(4346.46,1283.46) ; H5.8@5220.47,3035.43 5278.16,2977.74 5312.91,2977.74 5565,2725.65 5565,2491.02 5510.98,2437.01 pad.31@5496.06,2437.01 5493.34,2434.29 5459.29,2434.29 5405.51,2380.51 v1(5405.51,1814.96)
MM_SDIO_CLK: H5.11 pad.31@4625.98,2555.12 R26.2 R31.2 R41.1 U2.18 | length 2500
  Top Layer w10: R26.2@4563.92,2554.13 4707.68,2554.13 U2.18@4708.66,2555.12 4710.18,2553.6 v1(4773.38,2553.6) ; v1(4785,1940) 4785,1902.01 R31.2@4787.4,1899.61 ; v1(5125,1980) 5161.42,1943.58 R41.1@5161.42,1899.61
  Bottom Layer w10: pad.31@4625.98,2555.12 4624.1,2555.12 4606.24,2572.98 4606.24,2574.87 4570.87,2610.24 4570.87,2818.9 4897.64,3145.67 5060.24,3145.67 H5.11@5120.47,3085.43 ; v1(4773.38,2553.6) 4773.38,2293.38 4625,2145 4625,2045 4700,1970 4755,1970 v1(4785,1940) 4815,1910 4940,1910 5010,1980 v1(5125,1980)
MM_SDIO_CMD: H5.12 pad.31@4791.34,2787.4 R25.2 R32.2 R42.1 U2.21 | length 2084
  Top Layer w10: v1@4683.11,1937.65 4688.55,1932.21 4688.55,1900.03 R32.2@4688.98,1899.61 ; U2.21@4793.31,2698.82 4793.31,2785.43 pad.31@4791.34,2787.4 4791.34,2850.39 R25.2@4795.28,2854.33 ; v1(5020,1895) 5023.69,1895 5028.69,1900 5062.6,1900 R42.1@5062.99,1899.61
  Bottom Layer w10: v1(5020,1895) 4985,1860 4768.01,1860 4597.54,2030.47 4597.54,2152.66 4715,2270.12 4715,2711.06 pad.31@4791.34,2787.4 4791.34,2897.64 4895.46,3001.76 5085.96,3001.76 H5.12@5119.64,3035.43
  other v1: 4688.55,1939.46
MM_SDIO_D0: H5.13 pad.31@4625.98,2496.06 R24.2 R33.2 R43.1 U2.17 | length 2452.3
  Top Layer w10: v1(4560,2050) 4562.61,2047.39 4585.64,2047.39 4664.57,1968.46 4710.7,1968.46 v1(4738.94,1940.22) 4738.94,1900.35 R33.2@4738.19,1899.61 ; R24.2@4563.92,2495.08 4625,2495.08 pad.31@4625.98,2496.06 U2.17@4708.66,2496.06 ; v1(5050,1945) 5093.12,1945 5110.67,1927.45 5110.67,1901.14 R43.1@5112.2,1899.61
  Bottom Layer w10: v1(4560,2050) 4557.39,2052.61 4537.94,2052.61 4429.13,2161.42 4429.13,2429.13 4496.06,2496.06 pad.31@4625.98,2496.06 4665.35,2496.06 4681.1,2511.81 4681.1,2850.39 4952.76,3122.05 5033.86,3122.05 H5.13@5070.47,3085.43 ; v1(4738.94,1940.22) 4765.77,1913.39 4794.16,1885 4960,1885 5020,1945 v1(5050,1945)
MM_SDIO_D1: IC1.54 pad.31@4625.98,2437.01 R23.2 U2.16 | length 3120.1
  Top Layer w10: IC1.54@4019.21,1062.99 4090.8,1062.99 4093.2,1065.39 4093.32,1065.39 4100.13,1072.2 v1(4103.82,1072.2) ; v1(4185.04,1070.87) 4200.79,1086.61 4200.79,1196.85 4503.94,1500 4660,1500 4886.87,1726.87 4886.87,1946.16 4838.67,1994.36 4700.64,1994.36 v1(4560,2135) ; R23.2@4563.92,2436.02 4564.91,2437.01 pad.31@4625.98,2437.01 U2.16@4708.66,2437.01
  Bottom Layer w10: v1(4103.82,1072.2) 4183.71,1072.2 v1(4185.04,1070.87) ; v1(4560,2135) 4494.92,2135 4480.31,2149.61 4468.5,2161.42 4468.5,2177.11 cw(c4483.5,2177.11) 4483.5,2192.11 4558.3,2192.11 ccw(c4558.3,2207.11) 4558.3,2222.11 4468.92,2222.11 cw(c4468.92,2237.11) 4468.92,2252.11 4558.3,2252.11 ccw(c4558.3,2267.11) 4558.3,2282.11 4460.13,2282.11 cw(c4460.13,2297.11) 4460.13,2312.11 4558.3,2312.11 ccw(c4558.3,2327.11) 4558.3,2342.11 4483.5,2342.11 cw(c4483.5,2357.11) 4468.5,2357.11 4468.5,2381.57 4468.5,2401.57 4503.94,2437.01 pad.31@4625.98,2437.01
MM_SDIO_D2: IC1.89 pad.31@4909.45,2787.4 R3.2 R22.2 U2.23 | length 3001.1
  Top Layer w10: IC1.89@3693.98,1544.07 IC1.89@3694.71,1544.8 ; IC1.89@3694.88,1544.8 3695.61,1545.54 3695.61,1723.35 v1(3736.95,1764.68) 3737.14,1764.87 3737.14,1799.81 R3.2@3737.32,1800 ; U2.23@4911.42,2698.82 4911.42,2785.43 pad.31@4909.45,2787.4 4909.45,2850.39 R22.2@4913.39,2854.33 ; v1(4920,1700) 4920.31,1700.31 4920.31,1961.95 v1(4920.63,1962.26)
  Bottom Layer w10: v1(3736.95,1764.68) 3751.97,1779.7 3751.97,1779.9 3771.36,1799.28 4483.96,1799.28 4583.24,1700 v1(4920,1700) ; pad.31@4909.45,2787.4 4909.45,2317.53 4705,2113.08 4705,2060 4739.44,2025.56 4857.33,2025.56 v1(4920.63,1962.26)
MM_SDIO_D3: H5.14 IC1.90 pad.31@4850.39,2787.4 R21.2 U2.22 | length 3229.4
  Top Layer w10: IC1.90@3675.2,1544.8 v1@3675.22,1748.01 ; v1(4834,1942.67) 4834.5,1942.17 4834.5,1730.5 v1(4835,1730) ; U2.22@4852.36,2698.82 4852.36,2785.43 pad.31@4850.39,2787.4 4850.39,2850.39 R21.2@4854.33,2854.33 ; v1(4879.18,2934.3) 4944.07,2999.19 5034.23,2999.19 H5.14@5070.47,3035.43
  Bottom Layer w10: v1(3675.24,1748.03) 3675.24,1769.73 3732.28,1826.77 4503.94,1826.77 4600.71,1730 v1(4835,1730) ; v1(4834,1942.67) 4775.83,2000.83 4719.17,2000.83 4670.93,2049.07 4670.93,2110.93 4850.39,2290.39 pad.31@4850.39,2787.4 ; pad.31@4850.39,2789.28 4850.39,2905.51 v1(4879.18,2934.3)
MM_VBAT: C29.1 C30.1 H19.2 R46.1 U2.25 | length 7404.5
  Top Layer w10: v1(5540,2975) 5655,2860 R46.1@5655,2652.32
  Top Layer w30: v1(4996.06,2972.44) v1(5027.56,2972.44) 5029.53,2970.47 U2.25@5029.53,2698.82
  Middle Layer w10: v1(5027.56,2972.44) 5537.44,2972.44 v1(5540,2975)
  Middle Layer w50: H19.2@264,413 371,413 761,803 761,902 1169,1310 1305,1310 1760.62,1765.62 1950.66,1765.62 2051.18,1866.14 2051.18,2106.18 3149.72,3204.72 4696.45,3204.72 4928.73,2972.44 v1(4996.06,2972.44) v1(5027.56,2972.44)
MM_VDDIO: C31.1 H5.1 H22.2 R21.1 R22.1 R23.1 R24.1 R25.1 R26.1 U2.19 | length 7470.4
  Top Layer w23.62: R23.1@4529.28,2436.02 4530.06,2436.02 4530.46,2436.42 4530.46,2445.7 4531.5,2446.74 4531.5,2612.6 ; 4531.5,2614.33 4531.5,2616.86 ; 4570,3135 v1(4570,3100) ; U2.19@4708.66,2614.17 4705.98,2616.86 C31.1@4637.8,2616.86 4531.5,2616.86 ; R22.1@4913.39,2888.98 R21.1@4854.33,2888.98 R25.1@4795.28,2888.98 4570,2888.98 ; 4531.5,2616.86 4531.5,2850.47 4570,2888.98 ; 4570,2888.98 4570,3065 ; 4570,3065 v1(4570,3100) ; 4570,3065 v1(4535,3100) v1(4570,3100)
  Top Layer w35: v1(4535,3100) 4570,3135
  Top Layer w40: 4570,3135 4715,3280 5275,3280 5370.47,3184.53 H5.1@5370.47,3085.43
  Middle Layer w50: H22.2@638,414 716.05,414 1223.59,921.54 1223.59,1016.41 1887.17,1680 1971.84,1680 3392.87,3101.03 4533.97,3101.03 v1(4535,3100) v1(4570,3100)
MM_VFEM: H26.2 L2.2 R35.1 | length 8649
  Top Layer w10: v1(2555,1094.39) 2558.69,1094.39 2565.8,1087.27 3045.21,1087.27 3053.06,1095.11 3054.06,1095.11 3059.06,1100.11 R35.1@3059.06,1101.11
  Top Layer w23.62: L2.2@5599.68,2618.11 5599.68,2626.87 L2.2@5599.98,2627.17
  Top Layer w25: L2.2@5599.98,2627.17 v1(5599.98,2694.52)
  Middle Layer w50: v1@1320,1459 v1(1320,1496.5) 1320,1535 3092.97,3307.97 5408.57,3307.97 5600,3116.54 5600,2665
  Bottom Layer w10: 1320,1416 1586.39,1149.61 2500.39,1149.61 2555,1095 v1(2555,1094.39)
  Bottom Layer w50: H26.2@1107.88,515 1107.88,1203.88 1320,1416 1320,1459 v1(1320,1496.5)
  other v1: 1321,1459
MM_WAKE: H5.16 IC1.81 pad.31@5496.06,2377.95 U2.36 | length 4084.9
  Top Layer w10: IC1.81@3852.36,1544.8 3852.38,1640.42 3900.94,1688.98 4194.07,1688.98 v1(4264.46,1618.59) ; H5.16@5020.47,3035.43 4976.38,3079.53 4976.38,3110.24 5007.87,3141.73 5224.66,3141.73 5232.53,3133.86 v1(5236.22,3133.86) ; U2.36@5409.45,2377.95 pad.31@5496.06,2377.95
  Bottom Layer w10: v1(4264.46,1618.59) 4264.46,1618.14 4384.63,1497.97 4712.97,1497.97 4739.67,1524.67 4778.77,1524.67 4779.53,1523.9 4798.42,1523.9 4799.18,1524.67 5170.33,1524.67 5464.57,1818.9 5464.57,2141.73 5440.94,2165.35 5440.94,2355.94 5459.76,2374.76 5492.87,2374.76 pad.31@5496.06,2377.95 ; v1(5236.22,3133.86) 5386.14,3133.86 5455,3065 5455,2974.13 5650,2779.13 5650,2527.81 pad.31@5500.14,2377.95
NetC12_1: C12.1 C13.1 IC1.49 IC1.98 L1.1 | length 1125.6
  Top Layer w10: IC1.98@3517.72,1544.8 3517.72,1294.64 3674.78,1137.57 3782.9,1137.57 3931.1,989.37 3931.1,974.41 3937.01,980.31 3972.44,980.31 3988.19,964.57 C13.1@3988.19,914.96 3994.49,921.26 4023.62,921.26 4037.4,935.04 C12.1@4099.8,935.04 L1.1@4099.8,885.83 ; 3930.51,971.07 3930.51,936.11 IC1.49@3931.1,935.51
NetC22_1: C22.1 IC1.12 X1.3 | length 150.4
  Top Layer w10: X1.3@3301.18,1220.47 3303.15,1220.47 3314.57,1209.06 C22.1@3342.52,1209.06 3342.52,1236.22 3366.14,1259.84 IC1.12@3409.92,1259.84
NetC23_1: C23.1 IC1.13 X1.1 | length 295.1
  Top Layer w10: C23.1@3203.74,1183.66 3203.74,1182.4 3207.01,1179.13 X1.1@3248.03,1179.13 3250,1179.13 3259.76,1169.37 3259.76,1167.4 3273.8,1153.37 3350.22,1153.37 3366.14,1169.29 3366.14,1227.19 3378.2,1239.25 3409.02,1239.25 IC1.13@3409.92,1240.16 ; C23.1@3203.74,1183.96 C23.1@3207.01,1187.23
NetC25_2: C25.2 IC1.8 X2.2 | length 266
  Top Layer w10: X2.2@3204.72,1395.67 3207.17,1395.67 3216.93,1405.43 3216.93,1425.87 C25.2@3213.36,1425.87 ; X2.2@3208.66,1397.64 3220.39,1385.91 3232.2,1385.91 3271.41,1346.7 3279.53,1338.58 IC1.8@3409.92,1338.58
NetC26_2: C26.2 IC1.9 X2.1 | length 255.3
  Top Layer w10: C26.2@3192.52,1303.15 3192.52,1328.82 3202.28,1338.58 X2.1@3204.72,1338.58 3214.49,1328.82 3231.09,1328.82 3233.14,1326.77 3252.85,1326.77 3260.72,1318.9 IC1.9@3409.92,1318.9
NetC27_1: C27.1 C28.1 L2.1 U2.32 | length 155.1
  Top Layer w31.5: U2.32@5413.31,2618.04 U2.32@5409.45,2614.17 5480.31,2614.17 5519.69,2614.17 L2.1@5559.06,2614.17
NetC33_1: C33.1 C34.2 IC2.5 R47.2 | length 1560.6
  Top Layer w25: R47.2@4580.71,931.1 5238.9,931.1 v1(5240,930) ; v1(5445,1460) 5447.32,1462.32 C33.1@5447.32,1505 ; C33.1@5446.67,1505 5446.67,1549.67 C34.2@5447,1550 5504.01,1550 5518.41,1535.61 5571.48,1535.61 IC2.5@5575.59,1531.5
  Middle Layer w25: v1(5240,930) 5240,1355 5345,1460 v1(5445,1460)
